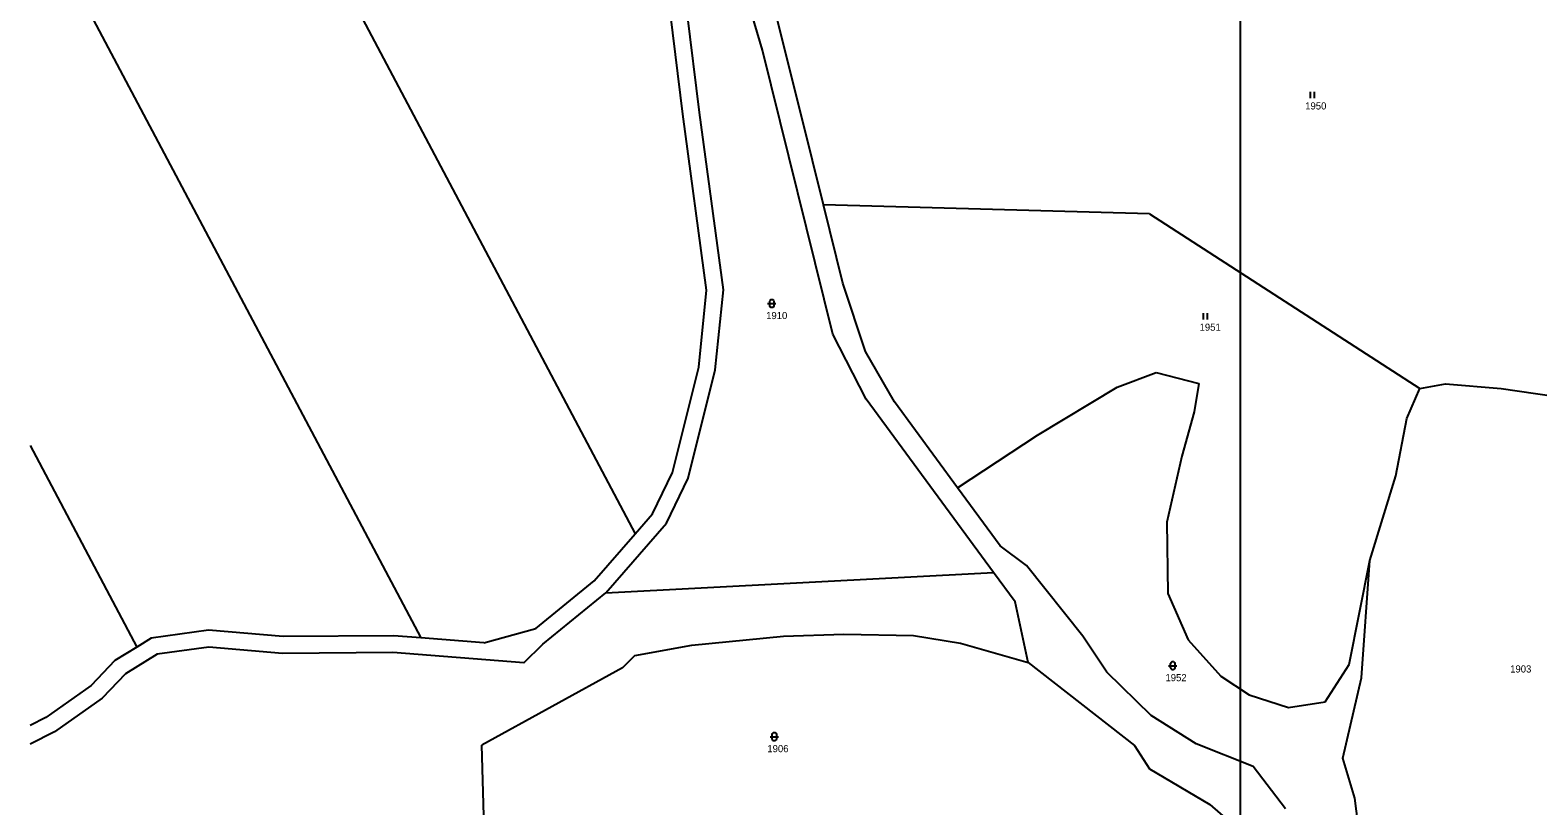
# Model space of a CAD drawing. Extents: x -801853 to -800578, y -1017479 to -1016338.
# Drawn here: x -801848 to -801488.1, y -1017172.4 to -1016987.3 of the extents above; entities that cross this region are included whole.
import ezdxf

# ---------------------------------------------------------------- set-up
doc = ezdxf.new("R2010")
doc.units = 0
for name, color, linetype in [('Default', 7, 'Continuous'), ('KN_HRANICE', 7, 'Continuous'), ('KN_KULTURY', 7, 'Continuous'), ('KN_PARCELY', 7, 'Continuous'), ('LEGENDA', 7, 'Continuous')]:
    doc.layers.add(name, color=color, linetype=linetype)

# ---------------------------------------------------------------- blocks, each defined once
blk = doc.blocks.new('306')
at = {"layer": 'Default'}
for p, q in [((-0.5, 1.5), (-0.5, 0)), ((0.5, 0), (0.5, 1.5))]:
    blk.add_line(p, q, dxfattribs=at)
blk = doc.blocks.new('316')
at = {"layer": 'Default'}
for points in [[(-1, 1), (0.27, 1), (1, 1)], [(-0.5, 1.5), (-0.4, 1.79), (-0.15, 1.97), (0.16, 1.97), (0.41, 1.79), (0.51, 1.5), (0.51, 0.5), (0.41, 0.21), (0.16, 0.03), (-0.15, 0.03), (-0.4, 0.21), (-0.5, 0.5), (-0.5, 1.5)]]:
    blk.add_lwpolyline(points, dxfattribs=at)

msp = doc.modelspace()

# ---------------------------------------------------------------- linework, layer by layer
at = {"layer": 'KN_HRANICE'}
for p, q in [((-801784.27, -1016955.14), (-801703.59, -1017107.44)), ((-801661.3, -1017018.39), (-801676.44, -1016957.72)), ((-801673.18, -1016992.05), (-801681.07, -1016965.55)), ((-801835.76, -1016979.41), (-801754.78, -1017132.31)), ((-801688.27, -1017006.93), (-801691.2, -1016983.13)), ((-801692.25, -1017007.35), (-801695.19, -1016983.45)), ((-801656.4, -1017059.84), (-801673.18, -1016992.05)), ((-801686.56, -1017049.34), (-801692.25, -1017007.35)), ((-801682.53, -1017049.27), (-801688.27, -1017006.93)), ((-801658.68, -1017029.01), (-801661.3, -1017018.39)), ((-801580.84, -1017031.1), (-801658.68, -1017029.01)), ((-801654.06, -1017047.7), (-801658.68, -1017029.01)), ((-801580.84, -1017031.1), (-801516.27, -1017072.8)), ((-801648.61, -1017063.96), (-801654.06, -1017047.7)), ((-801688.42, -1017067.67), (-801686.56, -1017049.34)), ((-801684.47, -1017068.36), (-801682.53, -1017049.27)), ((-801648.47, -1017075.34), (-801656.4, -1017059.84)), ((-801641.69, -1017076), (-801648.61, -1017063.96)), ((-801694.71, -1017092.82), (-801688.42, -1017067.67)), ((-801690.93, -1017094.18), (-801684.47, -1017068.36)), ((-801588.56, -1017072.48), (-801579.21, -1017069.02)), ((-801579.21, -1017069.02), (-801569.05, -1017071.63)), ((-801607.54, -1017083.93), (-801588.56, -1017072.48)), ((-801569.05, -1017071.63), (-801570.19, -1017078.34)), ((-801519.39, -1017079.95), (-801516.27, -1017072.8)), ((-801516.27, -1017072.8), (-801510.16, -1017071.7)), ((-801510.16, -1017071.7), (-801496.87, -1017072.82)), ((-801496.87, -1017072.82), (-801478.06, -1017075.54)), ((-801618.05, -1017116.71), (-801648.47, -1017075.34)), ((-801626.64, -1017096.51), (-801641.69, -1017076)), ((-801570.19, -1017078.34), (-801573.12, -1017088.9)), ((-801522.03, -1017093.64), (-801519.39, -1017079.95)), ((-801626.64, -1017096.51), (-801607.54, -1017083.93)), ((-801848.02, -1017086.43), (-801822.56, -1017134.47)), ((-801573.12, -1017088.9), (-801576.66, -1017104.66)), ((-801699.48, -1017102.72), (-801694.71, -1017092.82)), ((-801696.11, -1017104.95), (-801690.93, -1017094.18)), ((-801528.21, -1017113.81), (-801522.03, -1017093.64)), ((-801616.44, -1017110.33), (-801626.64, -1017096.51)), ((-801710.59, -1017121.54), (-801696.11, -1017104.95)), ((-801703.59, -1017107.44), (-801699.48, -1017102.72)), ((-801576.66, -1017104.66), (-801576.49, -1017121.72)), ((-801713.38, -1017118.65), (-801703.59, -1017107.44)), ((-801610.15, -1017115.02), (-801616.44, -1017110.33)), ((-801596.71, -1017131.88), (-801610.15, -1017115.02)), ((-801533.13, -1017138.67), (-801528.21, -1017113.81)), ((-801530.19, -1017141.81), (-801528.21, -1017113.81)), ((-801727.32, -1017130.01), (-801713.38, -1017118.65)), ((-801710.59, -1017121.54), (-801618.05, -1017116.71)), ((-801612.93, -1017123.67), (-801618.05, -1017116.71)), ((-801725.64, -1017133.8), (-801710.59, -1017121.54)), ((-801609.81, -1017138.16), (-801612.93, -1017123.67)), ((-801576.49, -1017121.72), (-801571.59, -1017132.79)), ((-801805.47, -1017130.48), (-801819.1, -1017132.33)), ((-801787.61, -1017131.99), (-801805.47, -1017130.48)), ((-801739.74, -1017133.5), (-801727.32, -1017130.01)), ((-801822.56, -1017134.47), (-801827.78, -1017137.72)), ((-801819.1, -1017132.33), (-801822.56, -1017134.47)), ((-801805.37, -1017134.5), (-801817.72, -1017136.18)), ((-801787.76, -1017135.99), (-801805.37, -1017134.5)), ((-801761.28, -1017131.8), (-801787.61, -1017131.99)), ((-801754.78, -1017132.31), (-801761.28, -1017131.8)), ((-801739.74, -1017133.5), (-801754.78, -1017132.31)), ((-801730.18, -1017138.26), (-801725.64, -1017133.8)), ((-801703.69, -1017136.49), (-801690.07, -1017134.01)), ((-801690.07, -1017134.01), (-801668.19, -1017131.9)), ((-801668.19, -1017131.9), (-801653.81, -1017131.39)), ((-801653.81, -1017131.39), (-801637.15, -1017131.68)), ((-801637.15, -1017131.68), (-801625.98, -1017133.55)), ((-801625.98, -1017133.55), (-801609.81, -1017138.16)), ((-801591.03, -1017140.5), (-801596.71, -1017131.88)), ((-801571.59, -1017132.79), (-801563.8, -1017141.41)), ((-801827.78, -1017137.72), (-801833.47, -1017143.63)), ((-801817.72, -1017136.18), (-801825.24, -1017140.85)), ((-801761.42, -1017135.8), (-801787.76, -1017135.99)), ((-801730.18, -1017138.26), (-801761.42, -1017135.8)), ((-801703.69, -1017136.49), (-801706.64, -1017139.46)), ((-801609.81, -1017138.16), (-801584.39, -1017157.99)), ((-801825.24, -1017140.85), (-801830.85, -1017146.68)), ((-801706.64, -1017139.46), (-801740.19, -1017157.87)), ((-801580.41, -1017150.78), (-801591.03, -1017140.5)), ((-801563.8, -1017141.41), (-801557.02, -1017145.9)), ((-801538.88, -1017147.55), (-801533.13, -1017138.67)), ((-801833.47, -1017143.63), (-801844.25, -1017151.25)), ((-801534.71, -1017160.98), (-801530.19, -1017141.81)), ((-801830.85, -1017146.68), (-801842.17, -1017154.68)), ((-801557.02, -1017145.9), (-801547.68, -1017148.92)), ((-801547.68, -1017148.92), (-801538.88, -1017147.55)), ((-801844.25, -1017151.25), (-801848.02, -1017153.16)), ((-801569.67, -1017157.56), (-801580.41, -1017150.78)), ((-801842.17, -1017154.68), (-801848.02, -1017157.64)), ((-801739.66, -1017177.55), (-801740.19, -1017157.87)), ((-801584.39, -1017157.99), (-801580.79, -1017163.54)), ((-801556.12, -1017162.99), (-801569.67, -1017157.56)), ((-801548.37, -1017173.06), (-801556.12, -1017162.99)), ((-801531.84, -1017170.53), (-801534.71, -1017160.98)), ((-801580.79, -1017163.54), (-801566.4, -1017172.05)), ((-801530.73, -1017179.18), (-801531.84, -1017170.53)), ((-801566.4, -1017172.05), (-801552.14, -1017184.41))]:
    msp.add_line(p, q, dxfattribs=at)
at = {"layer": 'LEGENDA'}
msp.add_lwpolyline([(-801559.16, -1017339.08), (-800718.16, -1017339.08), (-800718.16, -1016745.08), (-801559.16, -1016745.08)], close=True, dxfattribs=at)

# ---------------------------------------------------------------- block references
at = {"layer": 'KN_KULTURY'}
for name, p in [('306', (-801541.96, -1017003.54)), ('316', (-801670.99, -1017053.54)), ('306', (-801567.5, -1017056.32)), ('316', (-801575.28, -1017139.92)), ('316', (-801670.39, -1017156.86))]:
    msp.add_blockref(name, p, dxfattribs=at)

# ---------------------------------------------------------------- texts
at = {"layer": 'KN_PARCELY'}
for s, p in [('1950', (-801543.66, -1017006.24)), ('1910', (-801672.34, -1017056.24)), ('1951', (-801568.87, -1017059.02)), ('1952', (-801577.02, -1017142.62)), ('1903', (-801494.74, -1017140.55)), ('1906', (-801672.05, -1017159.56))]:
    msp.add_text(s, height=1.7, dxfattribs=at).set_placement(p)

doc.saveas('drawing.dxf')
